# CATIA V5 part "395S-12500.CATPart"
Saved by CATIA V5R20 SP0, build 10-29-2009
Part number: 395S-12500
Source: Unknown
Bounding box of the stored display mesh (mm): x -140 to 140, y -75 to 258, z -75 to 74.999
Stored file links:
  C:\Users\Utente\Desktop\3D files 395S\395S-12500.CATPart
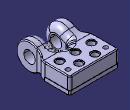
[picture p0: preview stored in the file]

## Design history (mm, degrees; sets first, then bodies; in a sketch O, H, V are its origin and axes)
Set1
  Line1 to Line3: stored without definition
  Point1 "Punto.4": stored without definition
Body1 (main body)
  Solid1 "PartBody": solid without history
Body2 "SPINE.1"
  Solid2: solid without history
Body3 "SPINE.2"
  Solid3: solid without history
